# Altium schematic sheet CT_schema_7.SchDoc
size 252 x 159 mm
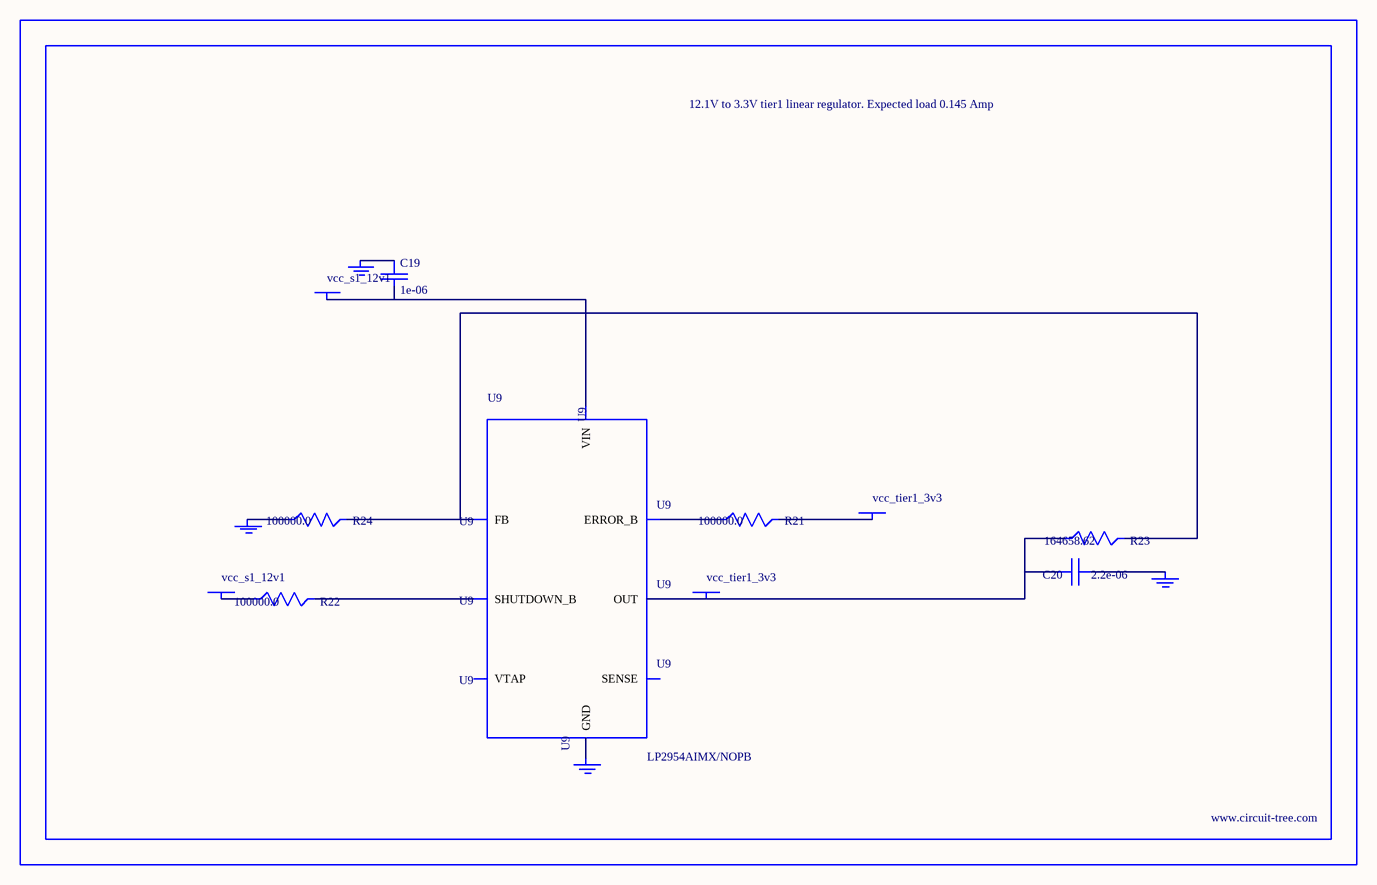
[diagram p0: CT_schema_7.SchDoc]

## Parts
BORDER6  (no value)
C19  1e-06  [EXV-9B]
C20  2.2e-06  [EXV-9B]
GND_INSTANCE_6_0  (no value)
GND_INSTANCE_6_1  (no value)
GND_INSTANCE_6_2  (no value)
GND_INSTANCE_6_3  (no value)
POWER_INSTANCE_6_0  vcc_s1_12v1
POWER_INSTANCE_6_1  vcc_tier1_3v3
POWER_INSTANCE_6_2  vcc_s1_12v1
POWER_INSTANCE_6_3  vcc_tier1_3v3
R21  100000.0  [R0603]
R22  100000.0  [R0603]
R23  164658.62  [R0603]
R24  100000.0  [R0603]
U9  LP2954AIMX/NOPB  [LP2954]

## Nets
NetC19_1: C19.1 GND_INSTANCE_6_2.0(GND)
NetC19_2: C19.2 POWER_INSTANCE_6_2.0(PWR) U9.8(VIN)
NetC20_1: C20.1 GND_INSTANCE_6_0.0(GND)
NetC20_2: C20.2 POWER_INSTANCE_6_3.0(PWR) R23.1 U9.1(OUT)
NetGND_INSTANCE_6_1_0: GND_INSTANCE_6_1.0(GND) R24.1
NetGND_INSTANCE_6_3_0: GND_INSTANCE_6_3.0(GND) U9.4(GND)
NetPOWER_INSTANCE_6_0_0: POWER_INSTANCE_6_0.0(PWR) R22.1
NetPOWER_INSTANCE_6_1_0: POWER_INSTANCE_6_1.0(PWR) R21.2
NetR21_1: R21.1 U9.5(ERROR_B)
NetR22_2: R22.2 U9.3(SHUTDOWN_B)
NetR23_2: R23.2 R24.2 U9.7(FB)

Not connected (* = marked no-connect by the designer): U9 2(SENSE) 6(VTAP)

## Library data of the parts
BORDER6 = BORDER_PAGE6
C19 = EDK105M050A9BAA
C20 = EDK225M050A9BAA
GND_INSTANCE_6_0-GND_INSTANCE_6_3 = GND
POWER_INSTANCE_6_0-POWER_INSTANCE_6_3 = PWR
R21 R22 R24 = RC0603JR-07100KL
R23 = R23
